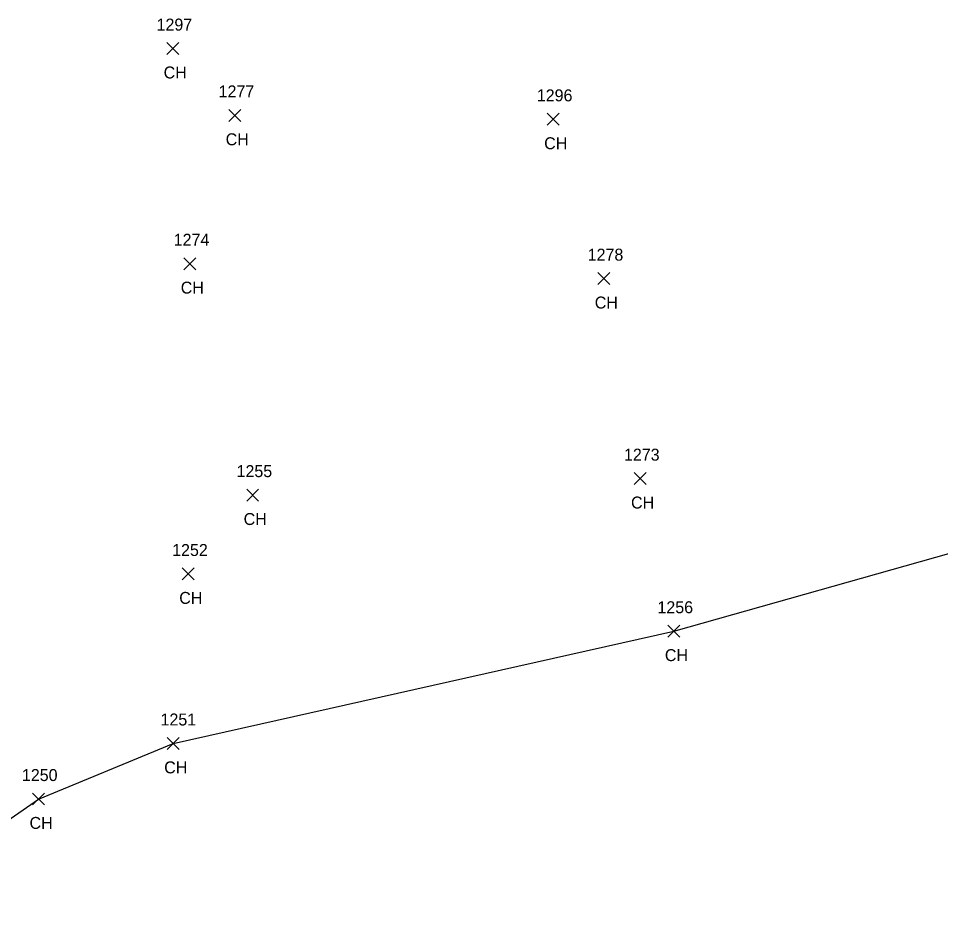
# Model space of a CAD drawing. Extents: x 1716490 to 1717645, y 888034 to 890004.
# Drawn here: x 1716912.5 to 1717066.5, y 888039 to 888188.7 of the extents above; entities that cross this region are included whole.
import ezdxf

# ---------------------------------------------------------------- set-up
doc = ezdxf.new("R2010")
doc.units = 0
for name, color, linetype in [('L_A', 7, 'Continuous'), ('L_I', 7, 'Continuous'), ('L_TIC', 7, 'Continuous'), ('LSOGP', 7, 'Continuous')]:
    doc.layers.add(name, color=color, linetype=linetype)

msp = doc.modelspace()

# ---------------------------------------------------------------- linework, layer by layer
at = {"layer": 'L_TIC'}
for points in [[(1716937.26, 888182.67), (1716939.26, 888184.67)], [(1716939.26, 888182.67), (1716937.26, 888184.67)], [(1716947.62, 888171.51), (1716949.62, 888173.51)], [(1716949.62, 888171.51), (1716947.62, 888173.51)], [(1717000.83, 888170.85), (1717002.83, 888172.85)], [(1717002.83, 888170.85), (1717000.83, 888172.85)], [(1716940.12, 888146.73), (1716942.12, 888148.73)], [(1716942.12, 888146.73), (1716940.12, 888148.73)], [(1717009.27, 888144.24), (1717011.27, 888146.24)], [(1717011.27, 888144.24), (1717009.27, 888146.24)], [(1717015.34, 888110.83), (1717017.34, 888112.83)], [(1717017.34, 888110.83), (1717015.34, 888112.83)], [(1716950.62, 888108.08), (1716952.62, 888110.08)], [(1716952.62, 888108.08), (1716950.62, 888110.08)], [(1716939.87, 888094.9), (1716941.87, 888096.9)], [(1716941.87, 888094.9), (1716939.87, 888096.9)], [(1717020.98, 888085.34), (1717022.98, 888087.34)], [(1717022.98, 888085.34), (1717020.98, 888087.34)], [(1716937.35, 888066.59), (1716939.35, 888068.59)], [(1716939.35, 888066.59), (1716937.35, 888068.59)], [(1716914.86, 888057.31), (1716916.86, 888059.31)], [(1716916.86, 888057.31), (1716914.86, 888059.31)]]:
    msp.add_lwpolyline(points, dxfattribs=at)
at = {"layer": 'LSOGP'}
msp.add_lwpolyline([(1716888.08, 888039.01), (1716915.87, 888058.3), (1716938.35, 888067.59), (1717021.98, 888086.34), (1717070.48, 888100.06)], dxfattribs=at)

# ---------------------------------------------------------------- texts
at = {"layer": 'L_A'}
for p in [(1716936.75, 888178.67), (1716947.11, 888167.51), (1717000.31, 888166.85), (1716939.61, 888142.73), (1717008.76, 888140.24), (1717014.82, 888106.83), (1716950.11, 888104.08), (1716939.36, 888090.9), (1717020.47, 888081.34), (1716936.84, 888062.59), (1716914.35, 888053.31)]:
    msp.add_text('CH', height=2, dxfattribs=at).set_placement(p)
at = {"layer": 'L_I'}
for s, p in [('1297', (1716935.57, 888186.67)), ('1277', (1716945.93, 888175.51)), ('1296', (1716999.08, 888174.85)), ('1274', (1716938.43, 888150.73)), ('1278', (1717007.58, 888148.24)), ('1273', (1717013.64, 888114.83)), ('1255', (1716948.93, 888112.08)), ('1252', (1716938.17, 888098.9)), ('1256', (1717019.23, 888089.34)), ('1251', (1716936.23, 888070.59)), ('1250', (1716913.08, 888061.31))]:
    msp.add_text(s, height=2, dxfattribs=at).set_placement(p)

doc.saveas('drawing.dxf')
